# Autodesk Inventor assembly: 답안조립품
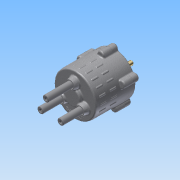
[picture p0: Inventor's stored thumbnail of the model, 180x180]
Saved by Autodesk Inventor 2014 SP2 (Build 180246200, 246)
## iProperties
Created: 2016-01
Part Number: 답안조립품
Document SubType Name: Assembly
Designer: Administrator
Mass: 2166.18 g
Surface Area: 1785.69 cm^2
Volume: 441.029 cm^3
Density: 4.91165 g/cm^3
Author: Administrator
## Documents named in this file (14)
- C:\Users\Administrator\Desktop\360105v1006\답안조립품.iam
- C:\Users\Administrator\Desktop\360105v1006\본체.ipt
- C:\Users\Administrator\Desktop\360105v1006\메인 축.ipt
- C:\Users\Administrator\Desktop\360105v1006\멈춤링 22 x 1.2.ipt
- C:\Users\Administrator\Desktop\360105v1006\멈춤링 10 x 1.ipt
- C:\Users\Administrator\Desktop\360105v1006\베어링 NA 4900.ipt
- C:\Users\Administrator\Desktop\360105v1006\판캠.ipt
- C:\Users\Administrator\Desktop\360105v1006\슬라이드 축.ipt
- C:\Users\Administrator\Desktop\360105v1006\가변 스프링-1.ipt
- C:\Users\Administrator\Desktop\360105v1006\가변 스프링-2.ipt
- C:\Users\Administrator\Desktop\360105v1006\가변 스프링-3.ipt
- C:\Users\Administrator\Desktop\360105v1006\오일실.ipt
- C:\Users\Administrator\Desktop\360105v1006\커버.ipt
- C:\Users\Administrator\Desktop\360105v1006\M5x0.8x20.ipt
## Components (8 placed, 4 different names)
1. 가변 스프링-1:1
2. 가변 스프링-2:1
3. 가변 스프링-3:1
4. M5x0.8x20:1
5. M5x0.8x20:2
6. M5x0.8x20:3
7. M5x0.8x20:4
8. M5x0.8x20:5
